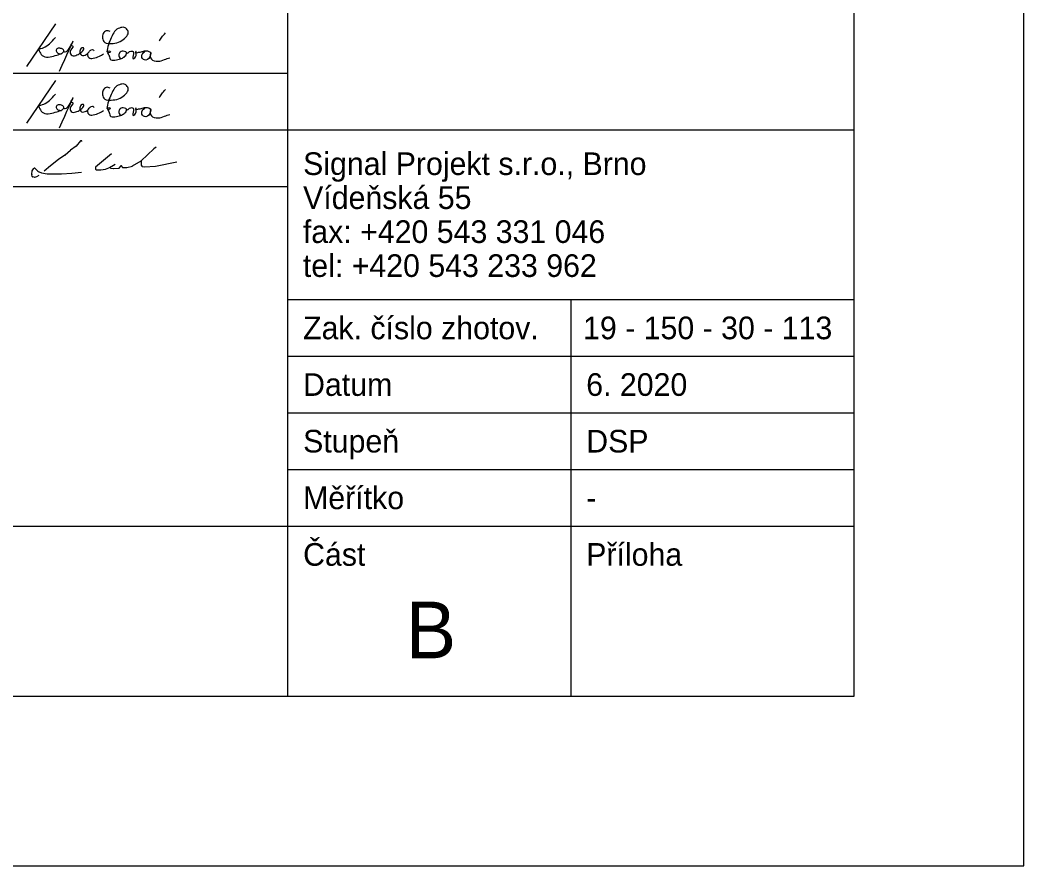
# Model space of a CAD drawing. Extents: x -790471 to -790261, y -984666 to -984369.
# Drawn here: x -790349.2 to -790260.6, y -984665.6 to -984590.9 of the extents above; entities that cross this region are included whole.
import ezdxf

# ---------------------------------------------------------------- set-up
doc = ezdxf.new("R2010")
doc.units = 0
for name, color, linetype in [('Deska žb', 7, 'Continuous'), ('Podpisy', 7, 'Continuous'), ('Ramečky', 7, 'Continuous'), ('Rámečky-tisk', 7, 'Continuous'), ('Text', 7, 'Continuous'), ('Text barevný', 7, 'Continuous')]:
    doc.layers.add(name, color=color, linetype=linetype)

# ---------------------------------------------------------------- blocks, each defined once
blk = doc.blocks.new('Lukášek')
at = {"layer": 'Deska žb'}
for points in [[(-658, 623), (-799, 512)], [(-538, 757), (-656, 625)], [(-526, 763), (-532, 761)], [(-502, 743), (-503, 750)], [(1060, 236), (1392, 554)], [(1393, 555), (1452, 601)], [(-1120, 270), (-1334, 99)], [(-949, 386), (-1119, 271)], [(-800, 511), (-947, 387)], [(277, 422), (-140, 71)], [(-1810, -20), (-1764, 37)], [(-1741, 39), (-1734, 34)], [(-1733, 32), (-1676, -31)], [(-1334, 99), (-1493, -40)], [(-146, 58), (-146, 41)], [(-146, 38), (-141, 12)], [(0, 0), (116, 16)], [(120, 17), (203, 49)], [(205, 50), (283, 92)], [(244, 59), (250, 49)], [(261, 42), (331, 30)], [(284, 93), (373, 148)], [(335, 30), (465, 39)], [(476, 45), (519, 96)], [(546, 94), (559, 68)], [(574, 60), (681, 63)], [(685, 63), (829, 98)], [(833, 100), (1057, 233)], [(1056, 231), (1056, 130)], [(1058, 121), (1075, 95)], [(1086, 88), (1147, 79)], [(1150, 79), (1434, 92)], [(1437, 93), (1997, 211)], [(-1825, -119), (-1813, -28)], [(-1809, -179), (-1825, -126)], [(-1757, -200), (-1797, -190)], [(-1700, -189), (-1749, -201)], [(-1634, -152), (-1695, -187)], [(-1672, -34), (-1636, -56)], [(-1633, -57), (-1570, -82)], [(-1567, -83), (-1418, -106)], [(-1415, -106), (-1252, -106), (-1041, -106)], [(-1040, -106), (-770, -93)], [(-769, -92), (-512, -66)], [(-127, -2), (-88, -6)], [(-85, -7), (-1, 0)]]:
    blk.add_lwpolyline(points, dxfattribs=at)
for centre, start, end in [((-669, 636), 308.3333, 317.9357), ((-525, 746), 113.9625, 137.9357), ((-519, 748), 6.3402, 113.9625), ((1403, 542), 127.875, 133.8427), ((-1110, 257), 123.9436, 128.6598), ((-958, 399), 303.9436, 310.1792), ((-789, 499), 128.3333, 130.1792), ((-1751, 26), 50.1944, 140.7106), ((-1745, 21), 41.9872, 50.1944), ((-1324, 86), 128.6598, 131.1859), ((-129, 58), 130.156, 180), ((-129, 41), 180, 189.4623), ((-125, 15), 189.4623, 262.875), ((-2, 16), 274.3987, 277.9072), ((114, 32), 277.9072, 291.0375), ((197, 64), 291.0375, 298.4429), ((264, 58), 210.9638, 260.5377), ((275, 107), 298.4429, 302.1957), ((334, 46), 260.5377, 274.0856), ((463, 55), 274.0856, 320.4403), ((531, 86), 27.8973, 140.4403), ((574, 76), 207.8973, 271.5911), ((681, 79), 271.5911, 283.7363), ((825, 114), 283.7363, 300.7189), ((1072, 130), 180, 212.4712), ((1049, 247), 300.7189, 313.8427), ((1089, 104), 212.4712, 261.8699), ((1149, 96), 261.8699, 272.6324), ((1433, 109), 272.6324, 281.9566), ((-1809, -121), 172.4054, 196.6992), ((-1797, -30), 140.7106, 172.4054), ((-1793, -175), 196.6992, 255.9638), ((-1753, -184), 255.9638, 283.2405), ((-1703, -173), 283.2405, 300.0686), ((-1664, -20), 221.9872, 239.7436), ((-1627, -41), 239.7436, 248.1986), ((-1564, -67), 248.1986, 261.3475), ((-1415, -89), 261.3475, 270), ((-1041, -89), 270, 272.7927), ((-771, -76), 272.7927, 275.856), ((-86, 10), 262.875, 274.3987)]:
    blk.add_arc(centre, 16.5, start, end, dxfattribs=at)

msp = doc.modelspace()

# ---------------------------------------------------------------- linework, layer by layer
for p, q in [((-790346.115, -984591.244), (-790348.663, -984595.025)), ((-790346.115, -984596.244), (-790348.663, -984600.025))]:
    msp.add_line(p, q)
for points in [[(-790341.279, -984591.932), (-790341.403, -984591.883), (-790341.624, -984591.795), (-790341.944, -984592.102), (-790341.988, -984592.492), (-790341.839, -984592.977), (-790341.182, -984593.004), (-790340.523, -984592.931), (-790339.963, -984592.552), (-790339.627, -984592.121), (-790339.743, -984591.755), (-790340.022, -984591.524), (-790340.448, -984591.591), (-790340.922, -984591.862), (-790341.175, -984592.482), (-790341.471, -984593.088), (-790341.534, -984593.538), (-790341.56, -984593.725)], [(-790336.941, -984592.767), (-790336.885, -984592.674), (-790336.731, -984592.417), (-790336.529, -984592.195), (-790336.4, -984592.053)], [(-790347.607, -984593.459), (-790347.471, -984593.438), (-790347.152, -984593.39), (-790346.617, -984593.051), (-790346.31, -984592.682), (-790346.12, -984592.454)], [(-790345.367, -984593.701), (-790345.331, -984593.727), (-790345.071, -984593.918), (-790344.193, -984591.983), (-790345.101, -984593.96), (-790345.793, -984595.466)], [(-790347.607, -984593.459), (-790347.564, -984593.581), (-790347.469, -984593.848), (-790347.105, -984594.265), (-790346.386, -984594.146), (-790345.871, -984593.982), (-790345.36, -984593.82), (-790345.358, -984593.503), (-790345.652, -984593.408), (-790345.966, -984593.372), (-790346.085, -984593.642), (-790345.908, -984593.896), (-790345.702, -984593.894), (-790345.586, -984593.893)], [(-790344.735, -984593.177), (-790344.686, -984593.177), (-790344.387, -984593.177), (-790344.935, -984593.693), (-790344.696, -984594.168), (-790344.167, -984593.993), (-790343.885, -984593.83), (-790343.466, -984593.455), (-790343.798, -984593.276), (-790344.006, -984593.671), (-790343.862, -984594.105), (-790343.352, -984593.997), (-790343.146, -984593.688), (-790342.94, -984593.53), (-790342.757, -984593.518), (-790342.732, -984593.588), (-790342.716, -984593.63)], [(-790343.286, -984593.868), (-790343.285, -984593.962), (-790343.284, -984594.133), (-790343.045, -984594.359), (-790342.5, -984594.261), (-790342.128, -984594.055), (-790341.867, -984593.911)], [(-790341.56, -984593.725), (-790341.52, -984593.687), (-790341.438, -984593.606), (-790341.14, -984593.722), (-790341.419, -984593.825), (-790341.509, -984593.807), (-790341.521, -984593.804)], [(-790341.521, -984593.804), (-790341.474, -984593.87), (-790341.357, -984594.031), (-790341.303, -984594.538), (-790340.687, -984594.428), (-790340.261, -984594.313), (-790339.98, -984594.166), (-790339.692, -984593.742), (-790340.293, -984593.598), (-790340.517, -984593.901), (-790340.533, -984594.2), (-790340.397, -984594.281), (-790340.337, -984594.317)], [(-790339.858, -984593.773), (-790339.824, -984593.81), (-790339.761, -984593.877), (-790339.618, -984593.774), (-790339.527, -984593.643), (-790339.088, -984593.646), (-790339.415, -984594.465), (-790338.967, -984594.238), (-790338.963, -984593.549), (-790339.087, -984593.805), (-790339.029, -984593.851), (-790338.865, -984593.772), (-790338.538, -984593.749), (-790338.168, -984593.582), (-790337.514, -984593.74), (-790337.986, -984594.599), (-790338.522, -984594.346), (-790338.486, -984593.912), (-790338.288, -984593.74), (-790338.187, -984593.652)], [(-790337.732, -984593.834), (-790337.744, -984594.022), (-790337.77, -984594.434), (-790337.02, -984594.633), (-790336.498, -984594.411), (-790336.141, -984594.288), (-790336.021, -984594.247)], [(-790341.279, -984596.932), (-790341.403, -984596.883), (-790341.624, -984596.795), (-790341.944, -984597.102), (-790341.988, -984597.492), (-790341.839, -984597.977), (-790341.182, -984598.004), (-790340.523, -984597.931), (-790339.963, -984597.552), (-790339.627, -984597.121), (-790339.743, -984596.755), (-790340.022, -984596.524), (-790340.448, -984596.591), (-790340.922, -984596.862), (-790341.175, -984597.482), (-790341.471, -984598.088), (-790341.534, -984598.538), (-790341.56, -984598.725)], [(-790336.941, -984597.767), (-790336.885, -984597.674), (-790336.731, -984597.417), (-790336.529, -984597.195), (-790336.4, -984597.053)], [(-790347.607, -984598.459), (-790347.471, -984598.438), (-790347.152, -984598.39), (-790346.617, -984598.051), (-790346.31, -984597.682), (-790346.12, -984597.454)], [(-790345.367, -984598.701), (-790345.331, -984598.727), (-790345.071, -984598.918), (-790344.193, -984596.983), (-790345.101, -984598.96), (-790345.793, -984600.466)], [(-790344.735, -984598.177), (-790344.686, -984598.177), (-790344.387, -984598.177), (-790344.935, -984598.693), (-790344.696, -984599.168), (-790344.167, -984598.993), (-790343.885, -984598.83), (-790343.466, -984598.455), (-790343.798, -984598.276), (-790344.006, -984598.671), (-790343.862, -984599.105), (-790343.352, -984598.997), (-790343.146, -984598.688), (-790342.94, -984598.53), (-790342.757, -984598.518), (-790342.732, -984598.588), (-790342.716, -984598.63)], [(-790347.607, -984598.459), (-790347.564, -984598.581), (-790347.469, -984598.848), (-790347.105, -984599.265), (-790346.386, -984599.146), (-790345.871, -984598.982), (-790345.36, -984598.82), (-790345.358, -984598.503), (-790345.652, -984598.408), (-790345.966, -984598.372), (-790346.085, -984598.642), (-790345.908, -984598.896), (-790345.702, -984598.894), (-790345.586, -984598.893)], [(-790343.286, -984598.868), (-790343.285, -984598.962), (-790343.284, -984599.133), (-790343.045, -984599.359), (-790342.5, -984599.261), (-790342.128, -984599.055), (-790341.867, -984598.911)], [(-790341.56, -984598.725), (-790341.52, -984598.687), (-790341.438, -984598.606), (-790341.14, -984598.722), (-790341.419, -984598.825), (-790341.509, -984598.807), (-790341.521, -984598.804)], [(-790341.521, -984598.804), (-790341.474, -984598.87), (-790341.357, -984599.031), (-790341.303, -984599.538), (-790340.687, -984599.428), (-790340.261, -984599.313), (-790339.98, -984599.166), (-790339.692, -984598.742), (-790340.293, -984598.598), (-790340.517, -984598.901), (-790340.533, -984599.2), (-790340.397, -984599.281), (-790340.337, -984599.317)], [(-790339.858, -984598.773), (-790339.824, -984598.81), (-790339.761, -984598.877), (-790339.618, -984598.774), (-790339.527, -984598.643), (-790339.088, -984598.646), (-790339.415, -984599.465), (-790338.967, -984599.238), (-790338.963, -984598.549), (-790339.087, -984598.805), (-790339.029, -984598.851), (-790338.865, -984598.772), (-790338.538, -984598.749), (-790338.168, -984598.582), (-790337.514, -984598.74), (-790337.986, -984599.599), (-790338.522, -984599.346), (-790338.486, -984598.912), (-790338.288, -984598.74), (-790338.187, -984598.652)], [(-790337.732, -984598.834), (-790337.744, -984599.022), (-790337.77, -984599.434), (-790337.02, -984599.633), (-790336.498, -984599.411), (-790336.141, -984599.288), (-790336.021, -984599.247)]]:
    msp.add_open_spline(points, degree=3)
at = {"layer": 'Ramečky'}
for p, q in [((-790325.592, -984650.601), (-790325.592, -984565.601)), ((-790275.592, -984650.601), (-790275.592, -984565.601)), ((-790455.592, -984595.601), (-790325.592, -984595.601)), ((-790455.592, -984600.601), (-790325.592, -984600.601)), ((-790455.592, -984605.601), (-790325.592, -984605.601)), ((-790325.592, -984615.601), (-790275.592, -984615.601)), ((-790325.592, -984620.601), (-790275.592, -984620.601)), ((-790325.592, -984625.601), (-790275.592, -984625.601)), ((-790325.592, -984630.601), (-790275.592, -984630.601)), ((-790455.592, -984635.601), (-790275.592, -984635.601)), ((-790455.592, -984650.601), (-790275.592, -984650.601))]:
    msp.add_line(p, q, dxfattribs=at)
for points in [[(-790325.592, -984600.601), (-790275.592, -984600.601)], [(-790300.592, -984615.601), (-790300.592, -984650.601)]]:
    msp.add_lwpolyline(points, dxfattribs=at)
at = {"layer": 'Rámečky-tisk'}
msp.add_lwpolyline([(-790470.592, -984665.601), (-790260.592, -984665.601), (-790260.592, -984368.601)], dxfattribs=at)

# ---------------------------------------------------------------- block references
at = {"layer": 'Podpisy', "xscale": 0.0033510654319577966, "yscale": 0.0033510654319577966}
msp.add_blockref('Lukášek', (-790342.091, -984604.135), dxfattribs=at)

# ---------------------------------------------------------------- texts
at = {"layer": 'Text'}
for s, p in [('Signal Projekt s.r.o., Brno', (-790324.243, -984604.601)), ('Vídeňská 55', (-790324.243, -984607.601)), ('fax: +420 543 331 046', (-790324.261, -984610.601)), ('tel: +420 543 233 962', (-790324.261, -984613.601)), ('Zak. číslo zhotov.', (-790324.242, -984619.101)), ('19 - 150 - 30 - 113', (-790299.52, -984619.101)), ('Datum', (-790324.242, -984624.101)), ('6. 2020', (-790299.242, -984624.101)), ('Stupeň', (-790324.242, -984629.101)), ('DSP', (-790299.242, -984629.101)), ('Měřítko', (-790324.242, -984634.101)), ('-', (-790299.242, -984634.101)), ('Část', (-790324.242, -984639.101)), ('Příloha', (-790299.242, -984639.101))]:
    msp.add_text(s, height=2, dxfattribs=at).set_placement(p)
at = {"layer": 'Text barevný'}
msp.add_text('B', height=5, dxfattribs=at).set_placement((-790315.188, -984647.267))

doc.saveas('drawing.dxf')
